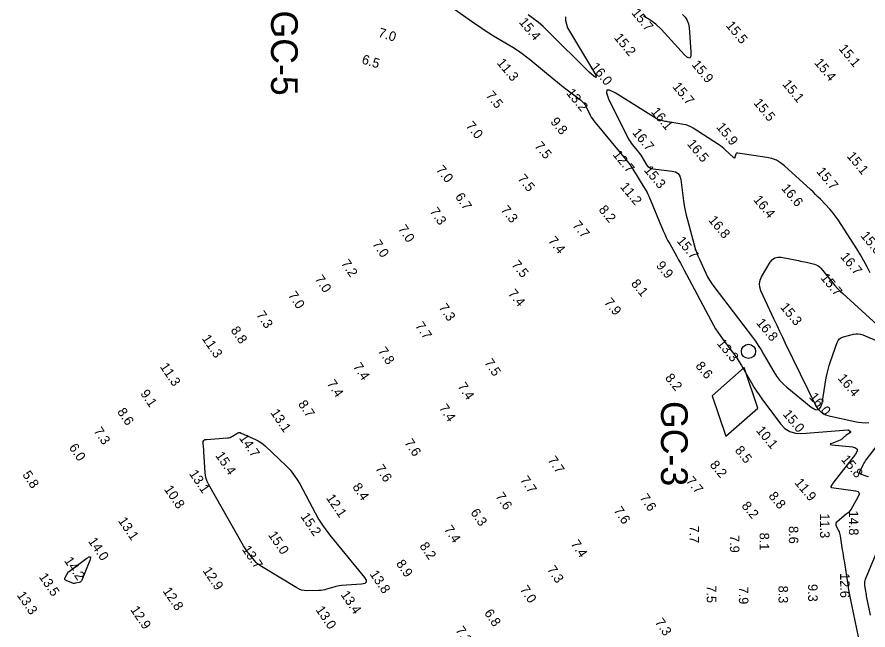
# Model space of a CAD drawing. Extents: x 824616 to 827440, y 158441 to 163197.
# Drawn here: x 826083.2 to 826529.7, y 160898.9 to 161220.6 of the extents above; entities that cross this region are included whole.
import ezdxf

# ---------------------------------------------------------------- set-up
doc = ezdxf.new("R2010")
doc.units = 0
for name, color, linetype in [('V-CHAN-CONT-EL14', 7, 'Continuous'), ('V-CHAN-CONT-EL16', 7, 'Continuous'), ('V-CHAN-NAID', 7, 'Continuous'), ('V-TOPO-SOUN', 7, 'Continuous')]:
    doc.layers.add(name, color=color, linetype=linetype)

msp = doc.modelspace()

# ---------------------------------------------------------------- linework, layer by layer
at = {"layer": 'V-CHAN-CONT-EL14'}
msp.add_lwpolyline([(826300.92, 161233.26), (826323.44, 161217.25), (826325.85, 161215.58), (826328.28, 161213.94), (826330.75, 161212.35), (826333.25, 161210.8), (826343.28, 161204.71), (826345.76, 161203.14), (826348.18, 161201.48), (826350.53, 161199.74), (826352.82, 161197.91), (826364.99, 161187.83), (826366.53, 161186.57), (826368.08, 161185.32), (826369.65, 161184.09), (826371.23, 161182.87), (826378.84, 161177.06), (826379.74, 161176.29), (826380.53, 161175.43), (826381.22, 161174.49), (826381.81, 161173.46), (826383.93, 161169.15), (826384.49, 161168.1), (826385.11, 161167.08), (826385.79, 161166.1), (826386.53, 161165.16), (826403.33, 161144.93), (826404.05, 161144.03), (826404.73, 161143.11), (826405.39, 161142.17), (826406.01, 161141.21), (826408.59, 161137.05), (826409.12, 161136.19), (826409.65, 161135.34), (826410.18, 161134.48), (826410.71, 161133.63), (826412.82, 161130.2), (826413.33, 161129.34), (826413.8, 161128.46), (826414.25, 161127.56), (826414.65, 161126.64), (826422.31, 161108.39), (826423.07, 161106.64), (826423.89, 161104.91), (826424.75, 161103.2), (826425.67, 161101.51), (826429.41, 161094.82), (826430.35, 161093.14), (826431.27, 161091.46), (826432.19, 161089.78), (826433.1, 161088.09), (826448.7, 161058.88), (826449.75, 161057.01), (826450.87, 161055.19), (826452.06, 161053.41), (826453.32, 161051.68), (826458.51, 161044.85), (826459.78, 161043.13), (826460.99, 161041.36), (826462.15, 161039.56), (826463.25, 161037.72), (826468.55, 161028.52), (826469.82, 161026.38), (826471.16, 161024.29), (826472.55, 161022.23), (826474, 161020.22), (826483.74, 161007.12), (826486.04, 161004.66), (826488.69, 161002.99), (826491.7, 161002.09), (826495.06, 161001.98), (826519.05, 161003.85), (826519.26, 161003.85), (826519.45, 161003.81), (826519.64, 161003.73), (826519.81, 161003.61), (826520.47, 161003.06), (826520.6, 161002.93), (826520.63, 161002.8), (826520.58, 161002.67), (826520.45, 161002.55), (826518.28, 161001.07), (826518, 161000.86), (826517.73, 161000.65), (826517.47, 161000.43), (826517.21, 161000.19), (826516.23, 160999.21), (826515.98, 160998.98), (826515.7, 160998.78), (826515.41, 160998.62), (826515.09, 160998.48), (826510.68, 160996.84), (826510.05, 160996.56), (826509.86, 160996.33), (826510.1, 160996.15), (826510.78, 160996.03), (826521.49, 160994.94), (826523.16, 160994.55), (826523.98, 160993.8), (826523.97, 160992.68), (826523.11, 160991.2), (826511.31, 160975.86), (826511.16, 160975.66), (826511.02, 160975.46), (826510.89, 160975.26), (826510.76, 160975.05), (826510.26, 160974.21), (826510.18, 160974.02), (826510.19, 160973.88), (826510.29, 160973.78), (826510.49, 160973.72), (826523.13, 160971.98), (826524.33, 160971.64), (826524.98, 160971.03), (826525.07, 160970.14), (826524.63, 160968.98), (826521.53, 160963.43), (826520.86, 160962.36), (826520.1, 160961.37), (826519.26, 160960.45), (826518.32, 160959.61), (826513.51, 160955.68), (826513.07, 160955.21), (826512.85, 160954.7), (826512.84, 160954.13), (826513.04, 160953.52), (826514.27, 160950.99), (826514.56, 160950.35), (826514.79, 160949.69), (826514.97, 160949.02), (826515.1, 160948.33), (826516.23, 160941), (826516.45, 160939.54), (826516.68, 160938.09), (826516.91, 160936.64), (826517.14, 160935.18), (826519.14, 160922.49), (826519.56, 160919.9), (826520.02, 160917.31), (826520.51, 160914.72), (826521.03, 160912.14), (826524.52, 160895.34)], dxfattribs=at)
for points in [[(826181.3, 160991.52), (826181.23, 160992.43), (826181.16, 160993.34), (826180.88, 160996.99), (826180.93, 160997.79), (826181.23, 160998.39), (826181.77, 160998.77), (826182.56, 160998.93), (826193.69, 160999.68), (826194.36, 160999.76), (826194.99, 160999.94), (826195.6, 161000.19), (826196.18, 161000.53), (826198.45, 161002.06), (826199.02, 161002.36), (826199.61, 161002.49), (826200.21, 161002.46), (826200.82, 161002.26), (826208.33, 160998.85), (826209.75, 160998.13), (826211.1, 160997.3), (826212.37, 160996.36), (826213.57, 160995.31), (826224.37, 160985.02), (826226.46, 160982.86), (826228.35, 160980.56), (826230.06, 160978.11), (826231.57, 160975.52), (826239.57, 160960.43), (826241.45, 160957.09), (826243.5, 160953.84), (826245.7, 160950.71), (826248.07, 160947.68), (826265.5, 160926.46), (826266.41, 160925.03), (826266.45, 160923.96), (826265.65, 160923.25), (826263.98, 160922.92), (826253.45, 160922.16), (826252.44, 160922.06), (826251.44, 160921.9), (826250.46, 160921.68), (826249.48, 160921.42), (826245.6, 160920.23), (826244.62, 160919.97), (826243.64, 160919.77), (826242.64, 160919.65), (826241.63, 160919.6), (826235.22, 160919.51), (826233.84, 160919.58), (826232.51, 160919.84), (826231.23, 160920.29), (826230, 160920.92), (826211.39, 160932.16), (826210.39, 160932.82), (826209.46, 160933.56), (826208.6, 160934.38), (826207.81, 160935.28), (826204.78, 160939.04), (826204.04, 160939.99), (826203.35, 160940.97), (826202.69, 160941.97), (826202.08, 160943.01), (826183.71, 160975.34), (826182.98, 160976.81), (826182.43, 160978.34), (826182.07, 160979.92), (826181.88, 160981.56), (826181.41, 160989.7), (826181.36, 160990.61)], [(826110.21, 160929.58), (826110.26, 160929.6), (826110.32, 160929.6), (826110.58, 160929.59), (826110.64, 160929.59), (826110.7, 160929.6), (826110.76, 160929.62), (826110.81, 160929.66), (826119.79, 160936.49), (826121.02, 160937.27), (826121.69, 160937.33), (826121.81, 160936.67), (826121.37, 160935.27), (826117.2, 160925.04), (826116.97, 160924.61), (826116.66, 160924.27), (826116.28, 160924.02), (826115.82, 160923.85), (826113.82, 160923.37), (826113.32, 160923.29), (826112.83, 160923.29), (826112.35, 160923.38), (826111.88, 160923.54), (826109.01, 160924.79), (826108.55, 160925.07), (826108.31, 160925.43), (826108.28, 160925.86), (826108.46, 160926.36), (826110.13, 160929.5), (826110.17, 160929.55)]]:
    msp.add_lwpolyline(points, close=True, dxfattribs=at)
at = {"layer": 'V-CHAN-CONT-EL16'}
for points in [[(826370.96, 161220.71), (826371.07, 161218.73), (826371.44, 161216.81), (826372.09, 161214.98), (826373, 161213.21), (826385.16, 161193.09), (826386.83, 161190.06), (826387.09, 161188.81), (826385.95, 161189.36), (826383.4, 161191.71), (826361.59, 161213.39), (826359.18, 161215.66), (826356.68, 161217.82), (826354.07, 161219.84), (826351.36, 161221.74)], [(826432.41, 161221.89), (826433.8, 161220.45), (826434.84, 161218.82), (826435.53, 161217.02), (826435.86, 161215.04), (826436.82, 161202.24), (826436.77, 161200.03), (826436.19, 161199.05), (826435.07, 161199.3), (826433.43, 161200.78), (826421.2, 161214.21), (826418.38, 161216.92), (826415.28, 161219.17), (826411.9, 161220.97)], [(826530.85, 161086.29), (826529.22, 161089.51), (826527.5, 161092.67), (826525.69, 161095.79), (826523.79, 161098.86), (826514.05, 161114.07), (826513.05, 161115.56), (826511.98, 161117), (826510.84, 161118.38), (826509.64, 161119.72), (826504.7, 161124.94), (826503.45, 161126.24), (826502.18, 161127.51), (826500.89, 161128.76), (826499.58, 161129.99), (826485.95, 161142.49), (826483.88, 161144.14), (826481.63, 161145.42), (826479.22, 161146.35), (826476.64, 161146.92), (826461.43, 161149.17), (826461.07, 161149.17), (826460.78, 161149.07), (826460.56, 161148.85), (826460.4, 161148.53), (826459.91, 161147.01), (826459.76, 161146.72), (826459.58, 161146.58), (826459.35, 161146.61), (826459.09, 161146.81), (826454.82, 161150.88), (826453.99, 161151.63), (826453.14, 161152.34), (826452.25, 161153.01), (826451.33, 161153.64), (826438.02, 161162.3), (826436.81, 161162.99), (826435.56, 161163.55), (826434.25, 161163.97), (826432.89, 161164.26), (826425.82, 161165.37), (826425.19, 161165.47), (826424.57, 161165.58), (826423.95, 161165.7), (826423.33, 161165.84), (826420.87, 161166.38), (826420.26, 161166.55), (826419.68, 161166.76), (826419.11, 161167.02), (826418.56, 161167.33), (826397.03, 161180.78), (826394.15, 161182.26), (826392.62, 161182.24), (826392.45, 161180.72), (826393.63, 161177.7), (826403.89, 161156.91), (826404.36, 161156.03), (826404.88, 161155.18), (826405.45, 161154.36), (826406.07, 161153.57), (826408.63, 161150.48), (826409.26, 161149.69), (826409.86, 161148.89), (826410.43, 161148.07), (826410.98, 161147.22), (826413.56, 161143.07), (826414.23, 161142.19), (826415.04, 161141.54), (826415.99, 161141.09), (826417.06, 161140.86), (826426.95, 161139.77), (826428.76, 161139.32), (826430.13, 161138.42), (826431.05, 161137.07), (826431.53, 161135.27), (826432.96, 161124.11), (826433.33, 161121.58), (826433.78, 161119.07), (826434.32, 161116.58), (826434.95, 161114.1), (826438.48, 161101.03), (826439.05, 161099.09), (826439.7, 161097.18), (826440.43, 161095.29), (826441.25, 161093.44), (826444.67, 161086.08), (826445.57, 161084.27), (826446.57, 161082.52), (826447.65, 161080.82), (826448.84, 161079.17), (826469.02, 161052.62), (826470.61, 161050.46), (826472.12, 161048.25), (826473.57, 161046), (826474.95, 161043.7), (826480.3, 161034.4), (826481.74, 161032.15), (826483.35, 161030.06), (826485.15, 161028.13), (826487.13, 161026.35), (826499.96, 161015.83), (826502.04, 161014.54), (826503.68, 161014.46), (826504.85, 161015.59), (826505.58, 161017.93), (826507.84, 161031.27), (826508.25, 161033.42), (826508.76, 161035.55), (826509.35, 161037.66), (826510.03, 161039.74), (826513.51, 161049.69), (826514.05, 161050.82), (826514.8, 161051.71), (826515.75, 161052.38), (826516.92, 161052.81), (826522.02, 161054.09), (826523.28, 161054.31), (826524.53, 161054.32), (826525.77, 161054.12), (826526.98, 161053.71), (826545.91, 161045.7)], [(826530.14, 161007.53), (826528.29, 161007.46), (826526.45, 161007.52), (826524.62, 161007.71), (826522.8, 161008.04), (826510.04, 161010.84), (826507.5, 161011.68), (826505.33, 161013), (826503.55, 161014.79), (826502.13, 161017.07), (826486.49, 161049.26), (826484.98, 161052.38), (826483.48, 161055.51), (826482, 161058.65), (826480.53, 161061.79), (826473.53, 161076.84), (826472.89, 161078.75), (826472.73, 161080.63), (826473.07, 161082.48), (826473.91, 161084.31), (826478.44, 161091.94), (826479.52, 161093.33), (826480.84, 161094.22), (826482.37, 161094.61), (826484.14, 161094.5), (826493.31, 161092.73), (826494.35, 161092.53), (826495.39, 161092.31), (826496.42, 161092.08), (826497.45, 161091.85), (826501.58, 161090.88), (826502.56, 161090.57), (826503.46, 161090.11), (826504.26, 161089.51), (826504.97, 161088.76), (826511.11, 161081.17), (826512.38, 161079.66), (826513.71, 161078.19), (826515.09, 161076.78), (826516.52, 161075.43), (826542.34, 161051.89)], [(826529.96, 160979.19), (826529.22, 160979.42), (826526.3, 160980.41), (826525.7, 160980.71), (826525.37, 160981.12), (826525.32, 160981.64), (826525.53, 160982.28), (826527.14, 160985.48), (826527.54, 160986.24), (826527.97, 160986.97), (826528.44, 160987.68), (826528.95, 160988.37), (826542.11, 161005.48)], [(826531.08, 160906.64), (826529.16, 160915.9), (826528.99, 160916.71), (826528.84, 160917.52), (826528.7, 160918.33), (826528.56, 160919.15), (826528.05, 160922.42), (826527.97, 160923.23), (826528.01, 160924.03), (826528.16, 160924.81), (826528.42, 160925.58), (826539.55, 160952.48)]]:
    msp.add_lwpolyline(points, dxfattribs=at)
at = {"layer": 'V-CHAN-NAID'}
msp.add_lwpolyline([(826464.74, 161036.65), (826447.86, 161021.81), (826455.06, 161000.52), (826471.94, 161015.36)], close=True, dxfattribs=at)
msp.add_circle((826467, 161045.08), 3.74, dxfattribs=at)

# ---------------------------------------------------------------- texts
for s, p in [('GC-5', (826216.49, 161224.02)), ('GC-3', (826421.11, 161019.05))]:
    msp.add_text(s, height=14, rotation=270, dxfattribs=at).set_placement(p)
at = {"layer": 'V-TOPO-SOUN'}
for s, rotation, p in [('15.7 ', 309.7, (826405.35, 161222.62)), ('15.4 ', 309.7, (826346.31, 161217.78)), ('15.5 ', 309.7, (826454.86, 161216.01)), ('7.0', 343.2, (826272.36, 161210.3)), ('15.2 ', 309.7, (826396.19, 161209.62)), ('15.1 ', 309.7, (826514.07, 161203.84)), ('6.5', 343.2, (826263.72, 161196.28)), ('11.3 ', 309.7, (826334.7, 161196.39)), ('16.0 ', 309.7, (826383.83, 161194.2)), ('15.9 ', 309.7, (826436.92, 161195.49)), ('15.4 ', 309.7, (826501.27, 161196.43)), ('15.7 ', 309.7, (826426.86, 161183.9)), ('15.1 ', 309.7, (826484.5, 161185.23)), ('7.5', 309.7, (826328.9, 161179.26)), ('13.2 ', 309.7, (826371.11, 161180.58)), ('15.5 ', 309.7, (826469.39, 161175.36)), ('16.1 ', 309.7, (826415.58, 161170.73)), ('9.8', 309.7, (826362.79, 161165.49)), ('7.0', 309.7, (826318.41, 161163.3)), ('15.9 ', 309.7, (826449.82, 161162.71)), ('16.7 ', 309.7, (826405.76, 161159.77)), ('7.5', 309.7, (826354.44, 161152.74)), ('16.5 ', 309.7, (826434.49, 161153.89)), ('12.7 ', 309.7, (826395.52, 161148.23)), ('15.1 ', 309.7, (826518.32, 161147.44)), ('7.0', 309.7, (826302.75, 161140.26)), ('15.3 ', 309.7, (826411.89, 161140.09)), ('15.7 ', 309.7, (826502.41, 161139.33)), ('7.5', 309.7, (826345.57, 161135.58)), ('11.2 ', 309.7, (826399.36, 161131.33)), ('16.6 ', 309.7, (826483.94, 161130.56)), ('6.7', 304.2, (826312.86, 161126.32)), ('16.4 ', 309.7, (826469.31, 161124.55)), ('7.3', 304.2, (826299.58, 161118.6)), ('7.3', 309.7, (826336.7, 161119.17)), ('8.2', 309.7, (826388.11, 161119.31)), ('7.7', 309.7, (826374.33, 161111.12)), ('16.8 ', 309.7, (826445.7, 161113.88)), ('7.0', 304.2, (826282.89, 161109.42)), ('7.4', 309.7, (826361.58, 161103)), ('15.7 ', 309.7, (826429.05, 161102.96)), ('15.6 ', 309.7, (826525.56, 161105.66)), ('7.0', 304.2, (826269.41, 161101.5)), ('16.7 ', 309.7, (826514.92, 161094.64)), ('7.2', 304.2, (826252.99, 161091.28)), ('7.5', 309.7, (826342.36, 161090.45)), ('9.9', 309.7, (826418.21, 161090)), ('7.0', 304.2, (826239.19, 161083.09)), ('8.1', 309.7, (826405.08, 161080.52)), ('15.7 ', 309.7, (826504.53, 161083.6)), ('7.4', 309.7, (826340.54, 161075.27)), ('7.0', 304.2, (826225.22, 161074.58)), ('7.3', 304.2, (826304.3, 161068.16)), ('7.9', 309.7, (826391, 161070.65)), ('15.3 ', 309.7, (826483.39, 161068.16)), ('7.3', 304.2, (826208.51, 161064.29)), ('7.7', 304.2, (826291.89, 161058.52)), ('16.8 ', 309.7, (826470.79, 161059.93)), ('8.8', 304.2, (826195.07, 161056.22)), ('11.3 ', 304.2, (826179.97, 161051.89)), ('13.3 ', 309.7, (826450.16, 161049.14)), ('7.8', 304.2, (826272.36, 161045.33)), ('11.3 ', 304.2, (826157.97, 161037.05)), ('7.4', 304.2, (826259.29, 161037.1)), ('7.5', 304.2, (826328.16, 161039.23)), ('8.6', 309.7, (826438.91, 161037.33)), ('8.2', 309.7, (826422.92, 161031.02)), ('7.4', 304.2, (826245.58, 161028.18)), ('7.4', 304.2, (826314.18, 161026.79)), ('16.4 ', 309.7, (826513.61, 161030.85)), ('9.1', 304.2, (826147.7, 161023.02)), ('16.0 ', 309.7, (826498.5, 161021.01)), ('8.7', 304.2, (826230.46, 161017.46)), ('7.4', 304.2, (826304.4, 161015.37)), ('8.6', 304.2, (826135.55, 161013.41)), ('13.1 ', 304.2, (826216, 161012.87)), ('15.0 ', 309.7, (826484.72, 161012.02)), ('7.3', 304.2, (826123.18, 161003.29)), ('10.1 ', 309.7, (826470.74, 161003.42)), ('14.7 ', 304.2, (826199.51, 160999.62)), ('7.6', 304.2, (826286.24, 160997.16)), ('6.0', 304.2, (826110.23, 160994.67)), ('8.5', 309.7, (826459.55, 160993.01)), ('15.4 ', 304.2, (826187.07, 160990.47)), ('7.7', 304.2, (826361.47, 160988.08)), ('15.8 ', 309.7, (826515.33, 160988.25)), ('7.6', 304.2, (826270.99, 160983.67)), ('8.2', 309.7, (826446.42, 160985.38)), ('5.8', 304.2, (826085.79, 160980.37)), ('13.1 ', 304.2, (826173.31, 160980.91)), ('7.7', 304.2, (826346.94, 160977.66)), ('7.7', 309.7, (826433.91, 160976.95)), ('8.4', 304.2, (826258.96, 160973.97)), ('11.9 ', 309.7, (826490.92, 160976.03)), ('10.8 ', 304.2, (826160.15, 160972.77)), ('7.6', 304.2, (826334.04, 160969.05)), ('8.8', 309.7, (826477.24, 160969.01)), ('12.1 ', 304.2, (826245.16, 160968.16)), ('7.6', 304.2, (826409.72, 160968.32)), ('6.3', 304.2, (826320.9, 160960.54)), ('7.6', 304.2, (826396.04, 160961.61)), ('8.2', 309.7, (826463.08, 160963.88)), ('13.1 ', 304.2, (826136.04, 160956.16)), ('15.2 ', 304.2, (826231.76, 160958.42)), ('11.3 ', 270.2, (826504.54, 160960.05)), ('14.8 ', 270.2, (826519.69, 160961.52)), ('7.4', 304.2, (826307.01, 160951.72)), ('7.7', 270.2, (826436.05, 160953.67)), ('8.6', 270.2, (826488.15, 160953.42)), ('15.0 ', 304.2, (826214.78, 160948.73)), ('8.1', 270.2, (826472.84, 160949.95)), ('14.0 ', 304.2, (826120.31, 160945.48)), ('8.2', 304.2, (826294.19, 160942.96)), ('7.4', 304.2, (826373.52, 160944.06)), ('7.9', 270.2, (826457.22, 160948.69)), ('13.7 ', 304.2, (826201.06, 160941.18)), ('14.2 ', 304.2, (826107.73, 160935.25)), ('8.9', 304.2, (826281.89, 160933.73)), ('12.9 ', 304.2, (826180.41, 160930)), ('7.3', 304.2, (826361.11, 160930.66)), ('13.5 ', 304.2, (826094.47, 160926.78)), ('13.8 ', 304.2, (826268.05, 160928.22)), ('12.6 ', 270.2, (826515.08, 160928.72)), ('7.0', 304.2, (826346.83, 160920.14)), ('7.5', 270.2, (826445.06, 160922.31)), ('8.3', 270.2, (826482.74, 160922.15)), ('9.3', 270.2, (826498.26, 160922.99)), ('13.3 ', 304.2, (826082.91, 160917.15)), ('12.8 ', 304.2, (826159.45, 160919.29)), ('13.4 ', 304.2, (826252.8, 160917.44)), ('7.9', 270.2, (826461.93, 160921.65)), ('12.9 ', 304.2, (826142.47, 160909.49)), ('13.0 ', 304.2, (826239.67, 160909.49)), ('6.8', 304.2, (826328.12, 160907.81)), ('7.3', 304.2, (826417.72, 160902.97)), ('7.2', 304.2, (826313.04, 160898.76))]:
    msp.add_text(s, height=5, rotation=rotation, dxfattribs=at).set_placement(p)

doc.saveas('drawing.dxf')
